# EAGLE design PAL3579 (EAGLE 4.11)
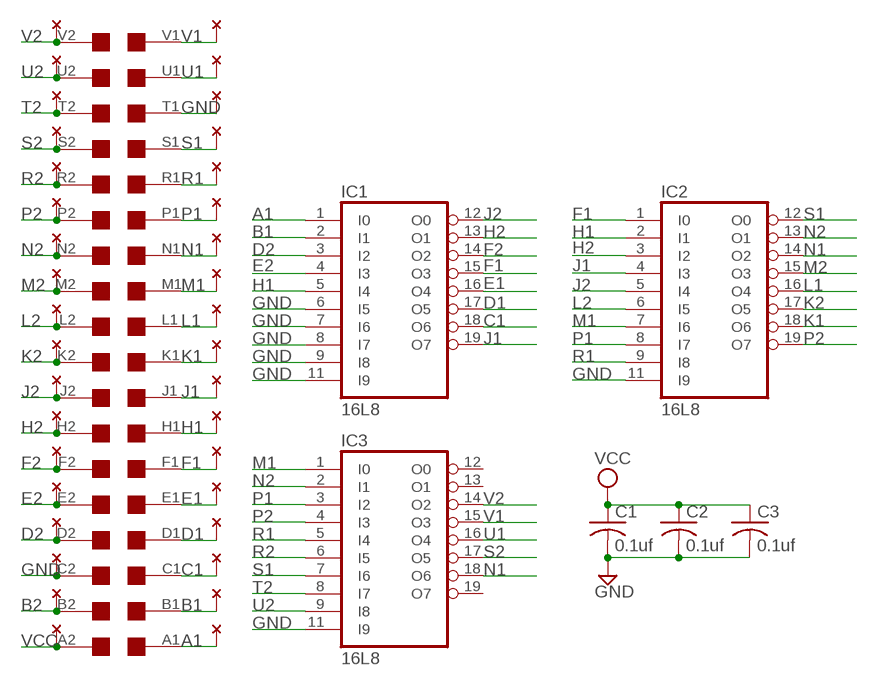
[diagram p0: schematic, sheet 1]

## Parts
C1  0.1uf  C-US050-025X075  [C050-025X075]
C2  0.1uf  C-US050-025X075  [C050-025X075]
C3  0.1uf  C-US050-025X075  [C050-025X075]
IC1  16L8  [DIL20]
IC2  16L8  [DIL20]
IC3  16L8  [DIL20]
U$1  EDGE-2  [EDGE-CON2]
U$4  THRU-HOLE2  [THRU-HOLEB]

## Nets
A1: IC1.1(I0) U$1.A1 U$4.A2
B1: IC1.2(I1) U$1.B1 U$4.B2
B2: U$1.B2 U$4.B1
C1: IC1.18(O6) U$1.C1 U$4.C2
D1: IC1.17(O5) U$1.D1 U$4.D2
D2: IC1.3(I2) U$1.D2 U$4.D1
E1: IC1.16(O4) U$1.E1 U$4.E2
E2: IC1.4(I3) U$1.E2 U$4.E1
F1: IC1.15(O3) IC2.1(I0) U$1.F1 U$4.F2
F2: IC1.14(O2) U$1.F2 U$4.F1
GND: C1.2 C2.2 C3.2 IC1.6(I5) IC1.7(I6) IC1.8(I7) IC1.9(I8) IC1.11(I9) IC2.11(I9) IC3.11(I9) U$1.C2 U$1.T1 U$4.C1 U$4.T2
H1: IC1.5(I4) IC2.2(I1) U$1.H1 U$4.H2
H2: IC1.13(O1) IC2.3(I2) U$1.H2 U$4.H1
J1: IC1.19(O7) IC2.4(I3) U$1.J1 U$4.J2
J2: IC1.12(O0) IC2.5(I4) U$1.J2 U$4.J1
K1: IC2.18(O6) U$1.K1 U$4.K2
K2: IC2.17(O5) U$1.K2 U$4.K1
L1: IC2.16(O4) U$1.L1 U$4.L2
L2: IC2.6(I5) U$1.L2 U$4.L1
M1: IC2.7(I6) IC3.1(I0) U$1.M1 U$4.M2
M2: IC2.15(O3) U$1.M2 U$4.M1
N1: IC2.14(O2) IC3.18(O6) U$1.N1 U$4.N2
N2: IC2.13(O1) IC3.2(I1) U$1.N2 U$4.N1
P1: IC2.8(I7) IC3.3(I2) U$1.P1 U$4.P2
P2: IC2.19(O7) IC3.4(I3) U$1.P2 U$4.P1
R1: IC2.9(I8) IC3.5(I4) U$1.R1 U$4.R2
R2: IC3.6(I5) U$1.R2 U$4.R1
S1: IC2.12(O0) IC3.7(I6) U$1.S1 U$4.S2
S2: IC3.17(O5) U$1.S2 U$4.S1
T2: IC3.8(I7) U$1.T2 U$4.T1
U1: IC3.16(O4) U$1.U1 U$4.U2
U2: IC3.9(I8) U$1.U2 U$4.U1
V1: IC3.15(O3) U$1.V1 U$4.V2
V2: IC3.14(O2) U$1.V2 U$4.V1
VCC: C1.1 C2.1 C3.1 U$1.A2 U$4.A1
Unconnected: IC3.12(O0) IC3.13(O1) IC3.19(O7)

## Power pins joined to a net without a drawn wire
GND: IC1.10(GND) IC2.10(GND) IC3.10(GND)
VCC: IC1.20(VCC) IC2.20(VCC) IC3.20(VCC)

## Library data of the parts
C1-C3 = rcl:C-US: CAPACITOR, American symbol
IC1-IC3 = pal:16L8: PAL
U$1 = dec-con:EDGE-2: Double-Sided DEC edge connector.
U$4 = dec-con:THRU-HOLE2: Thru-Hole addition to double-sided edge connector.

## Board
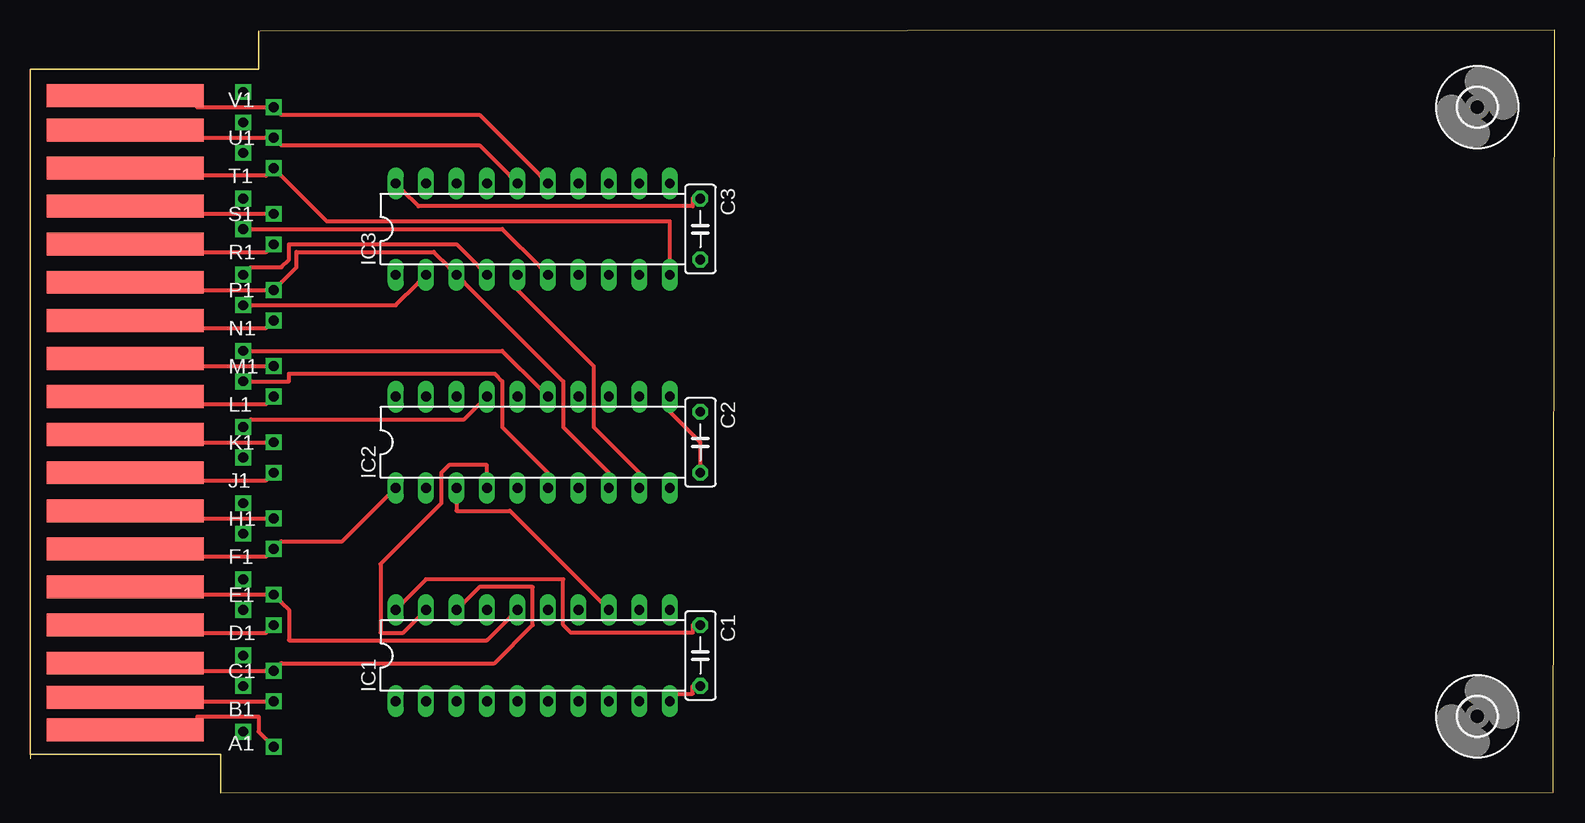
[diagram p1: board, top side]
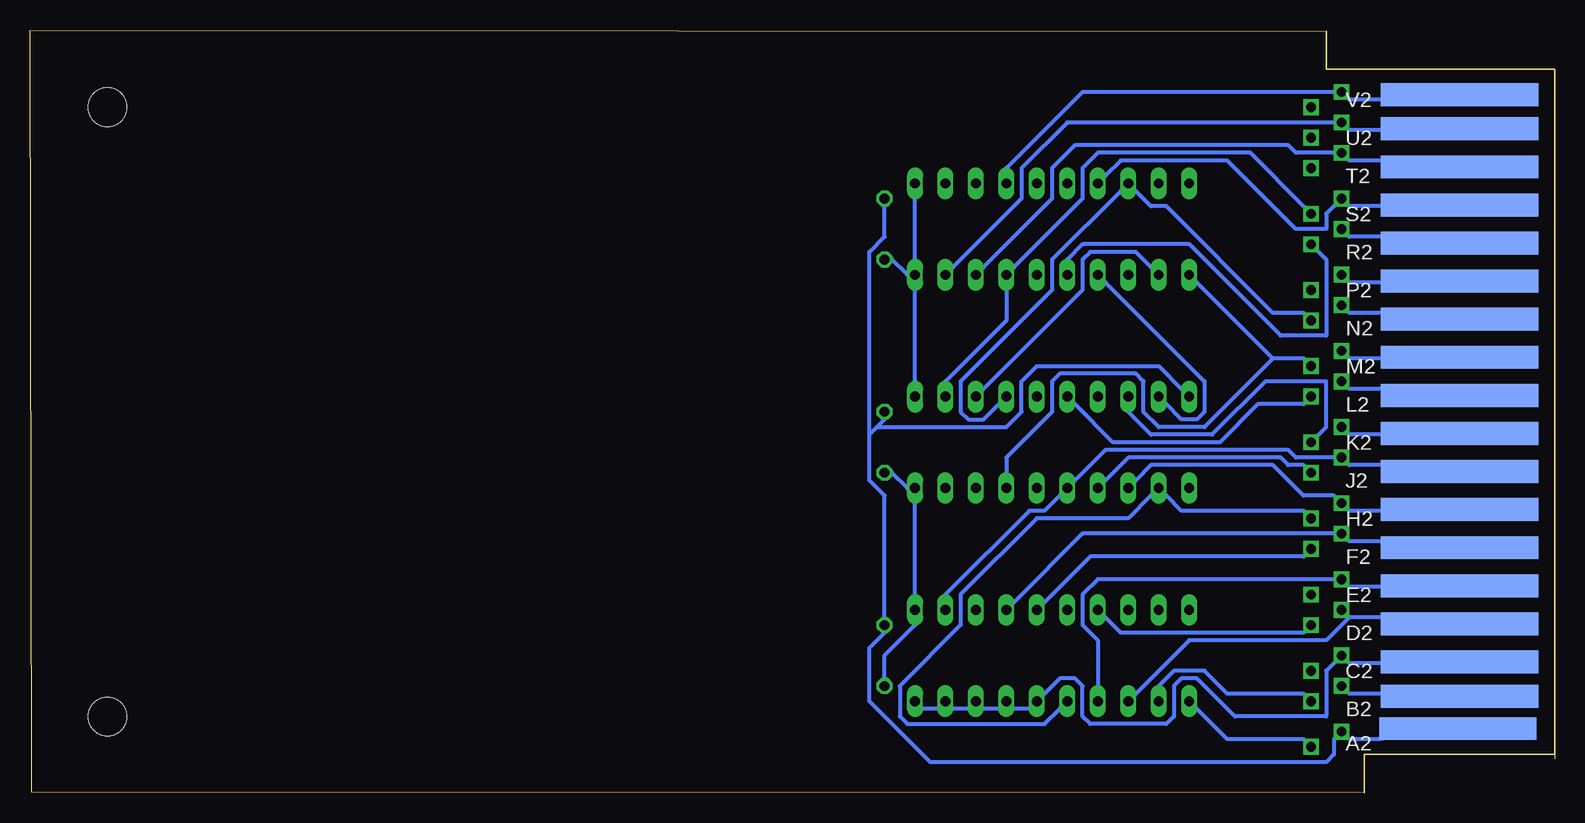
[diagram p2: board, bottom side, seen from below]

Size 127.11 x 63.59 mm. Coordinates in mm from the lower left corner, seen from the top.
Outline: 15.88,0 126.98,0.04 127.11,63.59 19.18,63.5
Outline: 0.01,59.65 0.01,2.83
Copper layers (1*16): Top 0.035mm / dielectric 1.5mm / Bottom 0.035mm
Design rules "10mils": minimum track width 13mil, minimum drill 28mil, track to track 10mil, track to pad 10mil, pad to pad 10mil, via to via 10mil, smd to smd 10mil, copper to edge 40mil, drill to drill 10mil, minimum pad ring 10mil, minimum via ring 8mil, stop-mask expansion 0mil, vias tented up to drill 0mil, thermal gap 10mil

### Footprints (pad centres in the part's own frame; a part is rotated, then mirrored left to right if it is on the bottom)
C050-025X075 = drill 0.813 octagon: 1 -2.54,0; 2 2.54,0
DIL20 = drill 0.813 long: 1 -11.43,-3.81; 2 -8.89,-3.81; 3 -6.35,-3.81; 4 -3.81,-3.81; 5 -1.27,-3.81; 6 1.27,-3.81; 7 3.81,-3.81; 8 6.35,-3.81; 9 8.89,-3.81; 10 11.43,-3.81; 11 11.43,3.81; 12 8.89,3.81; 13 6.35,3.81; 14 3.81,3.81; 15 1.27,3.81; 16 -1.27,3.81; 17 -3.81,3.81; 18 -6.35,3.81; 19 -8.89,3.81; 20 -11.43,3.81
EDGE-CON2 = smd 13.106 x 1.905: A1 7.938,5.239; B1 7.938,7.938; C1 7.938,10.795; D1 7.938,13.97; E1 7.938,17.145; F1 7.938,20.32; H1 7.938,23.495; J1 7.938,26.67; K1 7.938,29.845; L1 7.938,33.02; M1 7.938,36.195; N1 7.938,39.37; P1 7.938,42.545; R1 7.938,45.72; S1 7.938,48.895; T1 7.938,52.07; U1 7.938,55.245; V1 7.938,58.102 | smd 13.106 x 1.905 bottom: A2 8.096,5.34; B2 7.938,8.039; C2 7.938,10.897; D2 7.938,14.072; E2 7.938,17.247; F2 7.938,20.422; H2 7.938,23.597; J2 7.938,26.772; K2 7.938,29.947; L2 7.938,33.122; M2 7.938,36.297; N2 7.938,39.472; P2 7.938,42.647; R2 7.938,45.822; S2 7.938,48.997; T2 7.938,52.172; U2 7.938,55.347; V2 7.938,58.204
3,2 = hole 3.2: 0,0
THRU-HOLEB = drill 0.813 square: A1 17.78,5.08; A2 20.32,3.81; B1 17.78,8.89; B2 20.32,7.62; C1 17.78,11.43; C2 20.32,10.16; D1 17.78,15.24; D2 20.32,13.97; E1 17.78,17.78; E2 20.32,16.51; F1 17.78,21.59; F2 20.32,20.32; H1 17.78,24.13; H2 20.32,22.86; J1 17.78,27.94; J2 20.32,26.67; K1 17.78,30.48; K2 20.32,29.21; L1 17.78,34.29; L2 20.32,33.02; M1 17.78,36.83; M2 20.32,35.56; N1 17.78,40.64; N2 20.32,39.37; P1 17.78,43.18; P2 20.32,41.91; R1 17.78,46.99; R2 20.32,45.72; S1 17.78,49.53; S2 20.32,48.26; T1 17.78,53.34; T2 20.32,52.07; U1 17.78,55.88; U2 20.32,54.61; V1 17.78,58.42; V2 20.32,57.15

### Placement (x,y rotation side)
C1  55.88,11.43 270 top
C2  55.88,29.21 270 top
C3  55.88,46.99 270 top
IC1  41.91,11.43 0 top
IC2  41.91,29.21 0 top
IC3  41.91,46.99 0 top
U$1  0,0 0 top
U$2  [3,2]  120.65,6.35 0 top
U$3  [3,2]  120.65,57.15 0 top
U$4  0,0 0 top

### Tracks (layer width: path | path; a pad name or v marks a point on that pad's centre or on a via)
A1
  Top 0.33: U$4.A2 19.68,4.45 19.05,5.08 19.05,6.35 13.97,6.35 13.97,5.71 U$1.A1
  Bottom 0.33: U$4.A2 20.95,4.45 27.3,4.45 29.84,6.99 IC1.1
B1
  Top 0.33: U$4.B2 19.68,7.62 13.97,7.62 U$1.B1
  Bottom 0.33: U$4.B2 20.95,8.26 27.3,8.26 29.21,10.16 31.75,10.16 33.02,8.89 IC1.2
B2
  Bottom 0.33: U$4.B1 17.14,8.26 13.97,8.26 U$1.B2
C1
  Top 0.33: U$1.C1 13.97,10.16 19.68,10.16 U$4.C2 20.95,10.79 38.73,10.79 41.91,13.97 41.91,17.14 37.47,17.14 36.2,15.88 IC1.18
D1
  Top 0.33: U$4.D2 19.68,13.34 13.97,13.34 U$1.D1
  Bottom 0.33: U$4.D2 20.95,13.34 36.2,13.34 37.47,14.61 IC1.17
D2
  Bottom 0.33: 17.14,14.61 13.97,14.61 U$1.D2 | 17.14,14.61 U$4.D1 17.14,14.61 | 17.14,14.61 19.05,12.7 30.48,12.7 34.92,8.26 IC1.3
E1
  Top 0.33: U$1.E1 13.97,16.51 19.68,16.51 U$4.E2 20.95,15.88 21.59,15.24 21.59,12.7 38.1,12.7 40.01,14.61 IC1.16
E2
  Bottom 0.33: U$1.E2 13.97,17.14 17.14,17.14 U$4.E1 18.41,17.78 38.1,17.78 39.37,16.51 39.37,13.97 38.1,12.7 38.1,8.89 IC1.4
F1
  Top 0.33: IC2.1 29.84,24.77 26.04,20.95 20.95,20.95 U$4.F2 19.68,19.68 13.97,19.68 U$1.F1
  Bottom 0.33: IC1.15 42.55,15.88 38.73,19.68 20.95,19.68 U$4.F2
F2
  Bottom 0.33: U$1.F2 13.97,20.95 17.14,20.95 U$4.F1 18.41,21.59 39.37,21.59 45.09,15.88 IC1.14
GND
  Top 0.33: U$1.T1 13.97,51.44 19.68,51.44 U$4.T2 20.95,51.44 24.77,47.62 53.34,47.62 53.34,44.45 IC3.10 | IC1.10 53.98,8.26 55.24,8.26 55.24,8.89 C1.2 | IC2.11 53.34,31.75 55.88,29.21 55.88,27.3 C2.2
  Bottom 0.33: U$1.C2 13.97,10.79 17.14,10.79 U$4.C1 18.41,10.79 19.05,10.16 19.05,6.35 26.67,6.35 29.84,9.53 31.11,9.53 31.75,8.89 31.75,6.35 32.38,5.71 38.73,5.71 39.37,6.35 39.37,8.89 40.01,9.53 41.27,9.53 42.55,8.26 IC1.6 43.81,6.99 45.09,6.99 IC1.7 46.35,6.99 47.62,6.99 IC1.8 48.9,6.99 50.16,6.99 IC1.9 51.44,6.99 52.7,6.99 IC1.10 | IC2.11 53.34,34.29 53.34,41.91 IC3.10 | C3.2 55.24,44.45 53.98,43.18 IC3.10 | IC3.11 53.34,49.53 53.34,44.45 IC3.10 | C1.2 55.88,9.53 55.88,11.43 53.34,13.97 IC1.11 53.34,16.51 53.34,24.13 IC2.10 53.98,25.4 55.24,26.67 C2.2
H1
  Top 0.33: U$1.H1 13.97,22.86 19.68,22.86 U$4.H2
  Bottom 0.33: U$4.H2 20.95,23.5 31.11,23.5 32.38,24.77 IC2.2 33.66,24.77 35.56,22.86 43.18,22.86 49.53,16.51 49.53,13.97 54.61,8.89 54.61,6.35 53.98,5.71 42.55,5.71 41.27,6.99 IC1.5
H2
  Top 0.33: IC1.13 47.62,15.88 40.01,23.5 35.56,23.5 35.56,24.13 IC2.3
  Bottom 0.33: U$1.H2 13.97,23.5 17.14,23.5 U$4.H1 18.41,24.77 20.95,24.77 23.5,27.3 33.66,27.3 34.92,26.04 IC2.3
J1
  Top 0.33: IC1.19 32.38,14.61 31.11,13.34 29.21,13.34 29.21,19.05 34.29,24.13 34.29,26.67 34.92,27.3 38.1,27.3 38.1,26.67 IC2.4 | U$4.J2 19.68,26.04 13.97,26.04 U$1.J1
  Bottom 0.33: U$4.J2 20.95,27.3 22.23,27.3 22.86,27.94 35.56,27.94 37.47,26.04 IC2.4
J2
  Bottom 0.33: IC1.12 50.8,16.51 43.81,23.5 42.55,23.5 41.27,24.77 IC2.5 40.01,26.04 37.47,28.57 22.23,28.57 21.59,27.94 18.41,27.94 U$4.J1 17.14,27.3 13.97,27.3 U$1.J2
K1
  Top 0.33: U$4.K2 19.68,29.21 13.97,29.21 U$1.K1
  Bottom 0.33: IC2.18 35.56,31.75 33.66,29.84 28.57,29.84 24.13,34.29 19.05,34.29 19.05,30.48 19.68,29.84 U$4.K2
K2
  Top 0.33: IC2.17 37.47,32.38 36.2,31.11 18.41,31.11 U$4.K1
  Bottom 0.33: U$4.K1 17.14,29.84 13.97,29.84 U$1.K2
L1
  Top 0.33: U$4.L2 19.68,32.38 13.97,32.38 U$1.L1
  Bottom 0.33: U$4.L2 20.95,32.38 24.77,32.38 27.94,29.21 36.83,29.21 40.01,32.38 IC2.16
L2
  Top 0.33: IC2.6 43.18,26.67 39.37,30.48 39.37,34.29 38.73,34.92 21.59,34.92 21.59,34.29 18.41,34.29 U$4.L1
  Bottom 0.33: U$4.L1 17.14,33.66 13.97,33.66 U$1.L2
M1
  Top 0.33: U$1.M1 13.97,35.56 19.68,35.56 U$4.M2
  Bottom 0.33: 23.5,36.2 20.95,36.2 U$4.M2 | 23.5,36.2 29.84,42.55 IC3.1 | 23.5,36.2 29.21,30.48 33.02,30.48 34.29,31.75 34.29,34.29 34.92,34.92 41.27,34.92 41.91,34.29 41.91,31.75 45.72,27.94 45.72,26.67 IC2.7
M2
  Top 0.33: IC2.15 42.55,33.66 39.37,36.83 18.41,36.83 U$4.M1
  Bottom 0.33: U$4.M1 17.14,36.2 13.97,36.2 U$1.M2
N1
  Top 0.33: U$1.N1 13.97,38.73 19.68,38.73 U$4.N2
  Bottom 0.33: U$4.N2 20.95,40.01 23.5,40.01 32.38,48.9 33.66,48.9 34.92,50.16 IC3.18 36.2,50.16 41.91,44.45 41.91,41.91 49.53,34.29 49.53,31.75 48.9,31.11 47.62,31.11 46.35,32.38 IC2.14
N2
  Top 0.33: IC3.2 32.38,42.55 30.48,40.64 18.41,40.64 U$4.N1
  Bottom 0.33: IC2.13 47.62,33.66 39.37,41.91 39.37,44.45 38.73,45.09 34.92,45.09 33.66,43.81 IC3.2 | U$4.N1 17.14,40.01 13.97,40.01 U$1.N2
P1
  Top 0.33: IC2.8 48.26,26.67 44.45,30.48 44.45,34.29 36.2,42.55 IC3.3 34.92,43.81 33.66,45.09 22.23,45.09 22.23,43.81 20.95,42.55 U$4.P2 19.68,41.91 13.97,41.91 U$1.P1
P2
  Top 0.33: IC3.4 37.47,43.81 35.56,45.72 21.59,45.72 21.59,44.45 20.95,43.81 18.41,43.81 U$4.P1
  Bottom 0.33: IC2.19 32.38,32.38 31.11,31.11 29.84,31.11 29.21,31.75 29.21,34.29 37.47,42.55 IC3.4 | U$4.P1 17.14,42.55 13.97,42.55 U$1.P2
R1
  Top 0.33: IC2.9 50.8,26.67 46.99,30.48 46.99,35.56 40.64,41.91 IC3.5 | U$1.R1 13.97,45.09 19.68,45.09 U$4.R2
  Bottom 0.33: IC3.5 40.64,44.45 39.37,45.72 30.48,45.72 22.86,38.1 19.05,38.1 19.05,44.45 19.68,45.09 U$4.R2
R2
  Top 0.33: IC3.6 42.55,43.81 39.37,46.99 18.41,46.99 U$4.R1
  Bottom 0.33: U$4.R1 17.14,46.35 13.97,46.35 U$1.R2
S1
  Top 0.33: U$4.S2 19.68,48.26 13.97,48.26 U$1.S1
  Bottom 0.33: IC2.12 50.8,34.29 45.72,39.37 45.72,41.91 IC3.7 45.09,43.81 39.37,49.53 39.37,52.07 38.1,53.34 25.4,53.34 20.95,48.9 U$4.S2
S2
  Bottom 0.33: U$1.S2 13.97,48.9 17.14,48.9 U$4.S1 18.41,48.9 19.05,48.26 19.05,46.99 21.59,46.99 27.3,52.7 36.2,52.7 37.47,51.44 IC3.17
T2
  Bottom 0.33: U$1.T2 13.97,52.7 17.14,52.7 U$4.T1 18.41,53.34 21.59,53.34 22.23,53.98 40.01,53.98 41.91,52.07 41.91,49.53 47.62,43.81 IC3.8
U1
  Top 0.33: U$1.U1 13.97,54.61 19.68,54.61 U$4.U2 20.95,53.98 37.47,53.98 40.01,51.44 IC3.16
U2
  Bottom 0.33: U$1.U2 13.97,55.24 17.14,55.24 U$4.U1 18.41,55.88 40.64,55.88 44.45,52.07 44.45,49.53 50.16,43.81 IC3.9
V1
  Top 0.33: U$1.V1 13.97,57.78 13.97,57.15 19.68,57.15 U$4.V2 20.95,56.52 37.47,56.52 42.55,51.44 IC3.15
V2
  Bottom 0.33: U$1.V2 13.97,57.78 17.14,57.78 U$4.V1 18.41,58.42 39.37,58.42 45.72,52.07 IC3.14
VCC
  Top 0.33: IC1.20 31.11,15.88 33.02,17.78 44.45,17.78 44.45,13.97 45.09,13.34 55.24,13.34 55.24,13.97 C1.1 | IC3.20 31.11,50.16 32.38,48.9 55.24,48.9 55.24,49.53 C3.1
  Bottom 0.33: U$1.A2 14.61,4.45 17.14,4.45 U$4.A1 18.41,4.45 18.41,3.17 19.05,2.54 52.07,2.54 57.15,7.62 57.15,12.06 55.88,13.34 C1.1 55.88,14.61 55.88,24.77 57.15,26.04 57.15,29.84 | 56.52,30.48 55.88,31.11 C2.1 | 57.15,29.84 56.52,30.48 | 56.52,30.48 45.72,30.48 44.45,31.75 44.45,34.29 43.18,35.56 33.02,35.56 31.11,33.66 IC2.20 | 57.15,29.84 57.15,45.09 55.88,46.35 55.88,48.9 C3.1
